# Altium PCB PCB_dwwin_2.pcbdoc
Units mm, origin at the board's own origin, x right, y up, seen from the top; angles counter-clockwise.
Board outline 160.3 x 97.45 mm, 2 copper layers (Top Layer, Bottom Layer); 27 components, 25 nets, 175 pads, 0 vias.
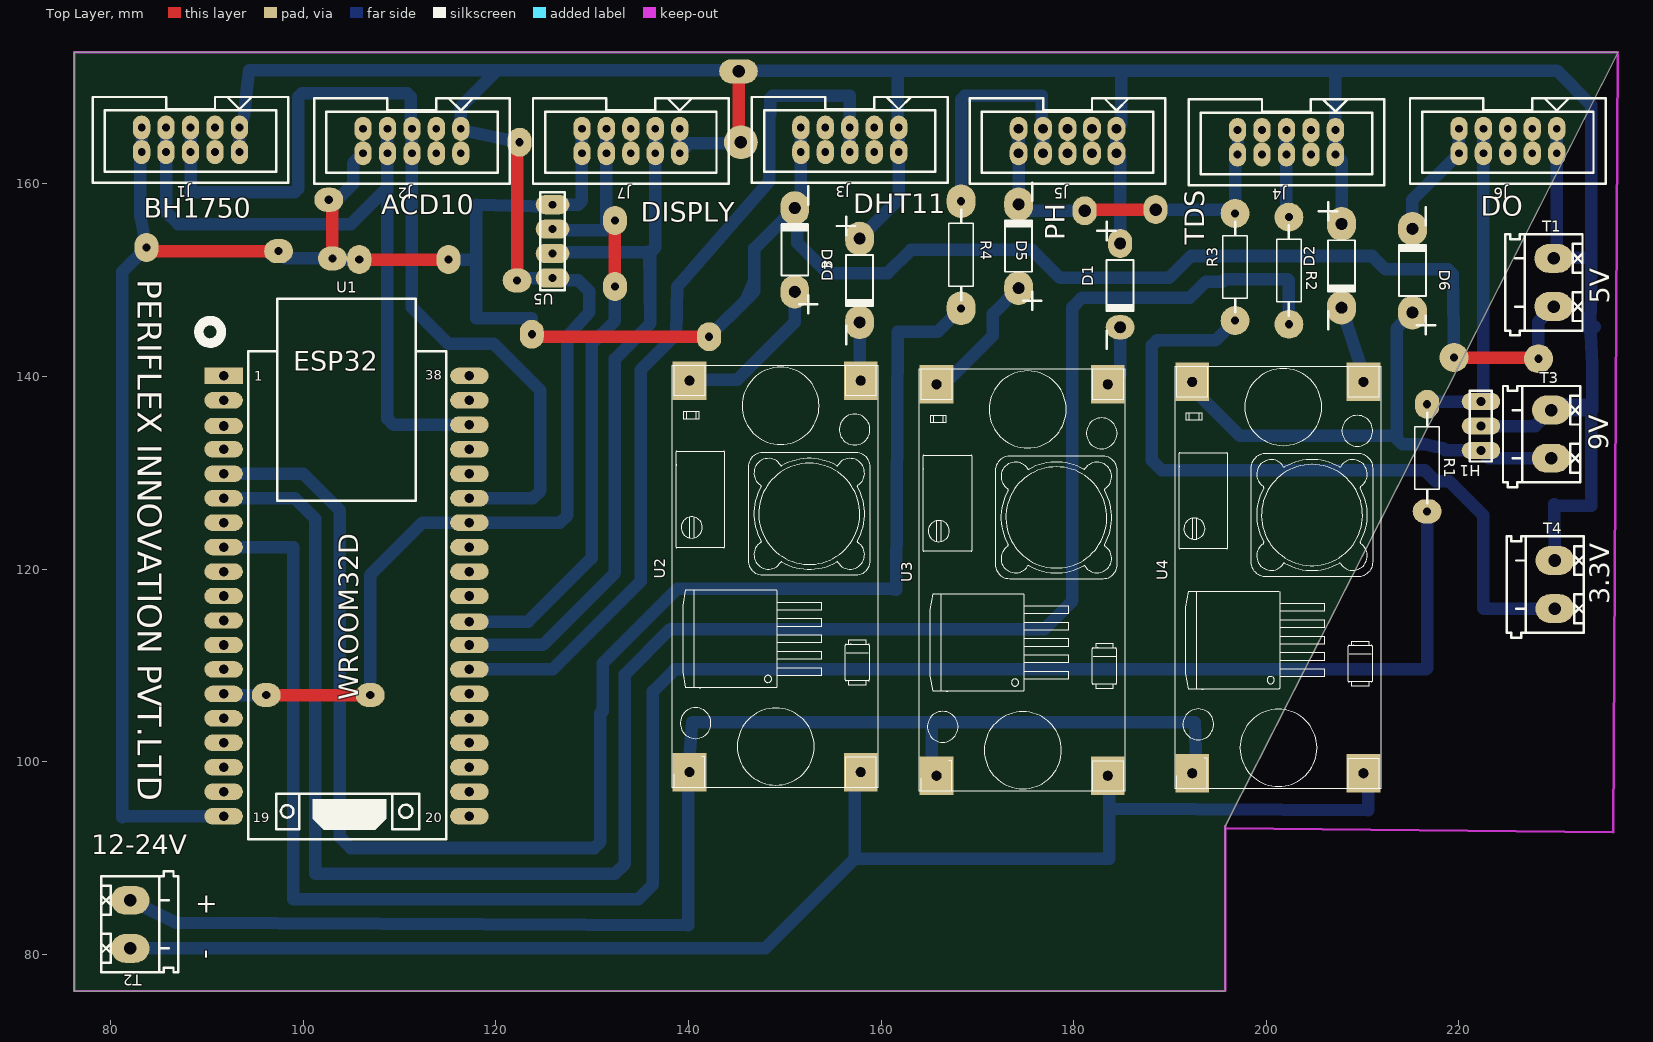
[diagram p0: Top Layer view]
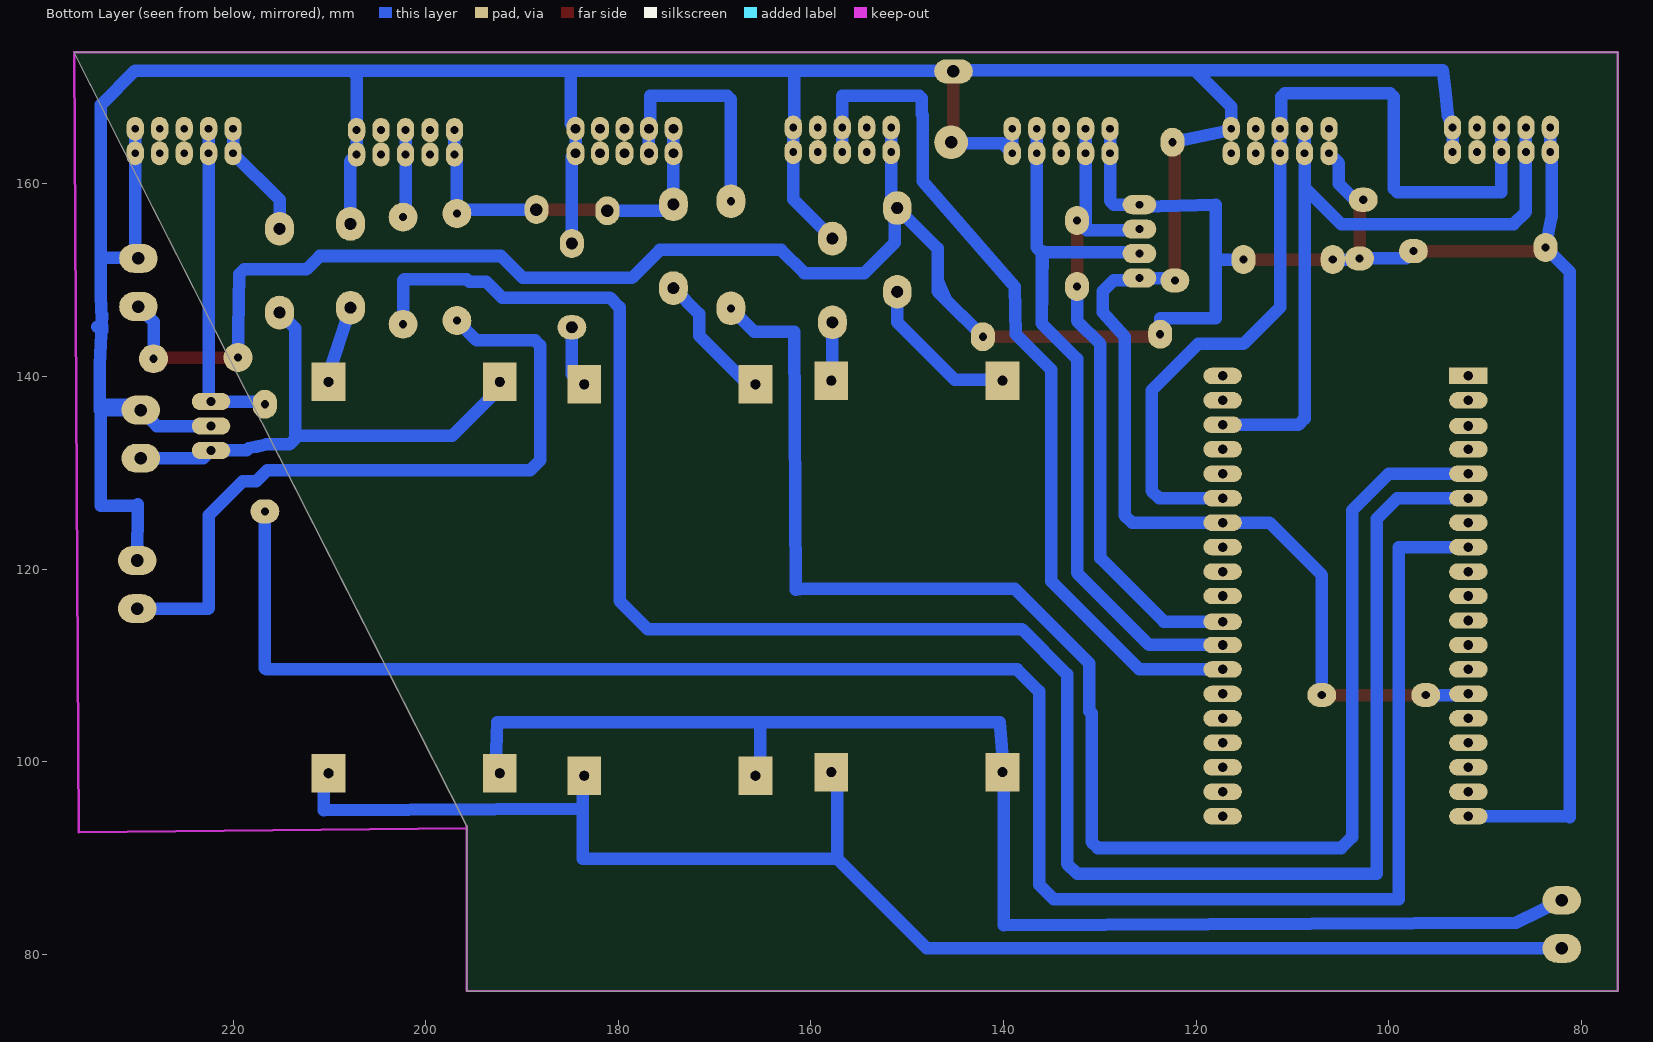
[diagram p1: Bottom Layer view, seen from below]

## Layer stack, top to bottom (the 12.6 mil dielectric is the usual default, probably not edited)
Top Layer: signal copper (thickness not stored)
Dielectric: dielectric 0.32, FR-4, Dk 4.8
Bottom Layer: signal copper (thickness not stored)

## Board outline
195.738,93.335 195.738,76.2 76.2,76.2 76.2,173.655 236.505,173.655

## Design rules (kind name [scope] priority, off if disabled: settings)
BoardOutlineClearance Default [All] p0: genericclearance=0.254 ignorepadtopadclearanceinfootprint=FALSE except(0: Region-CutoutEdge Arc-SplitContinuation Track-SplitContinuation SMDPad-SplitContinuation THPad-SplitContinuation Via-SplitContinuation Fill-SplitContinuation Poly-SplitContinuation Region-SplitContinuation Text-SplitContinuation; 0.5: Track-OutlineEdge SMDPad-OutlineEdge THPad-OutlineEdge Via-OutlineEdge Fill-OutlineEdge Region-OutlineEdge Poly-OutlineEdge Text-OutlineEdge Sheet-OutlineEdge Hole-OutlineEdge Track-CutoutEdge SMDPad-CutoutEdge THPad-CutoutEdge Via-CutoutEdge Fill-CutoutEdge Poly-CutoutEdge Text-CutoutEdge Sheet-CutoutEdge Hole-CutoutEdge)
Clearance Default [All] p1: gap=0.178 ignorepadtopadclearanceinfootprint=FALSE except(0: Region-Region; 0.5: Track-Track SMDPad-Track THPad-Track Via-Track Fill-Track Region-Track Poly-Track Text-Track Sheet-Track Hole-Track Track-SMDPad SMDPad-SMDPad THPad-SMDPad Via-SMDPad Fill-SMDPad Region-SMDPad Poly-SMDPad Text-SMDPad Sheet-SMDPad Hole-SMDPad Track-THPad SMDPad-THPad THPad-THPad Via-THPad Fill-THPad Region-THPad Poly-THPad Text-THPad Sheet-THPad Hole-THPad Track-Via SMDPad-Via THPad-Via Via-Via Fill-Via Region-Via Poly-Via Text-Via Sheet-Via Hole-Via Track-Fill SMDPad-Fill THPad-Fill Via-Fill Fill-Fill Region-Fill Poly-Fill Text-Fill Sheet-Fill Hole-Fill Track-Region SMDPad-Region THPad-Region Via-Region Fill-Region Poly-Region Text-Region Sheet-Region Hole-Region Track-Poly SMDPad-Poly THPad-Poly Via-Poly Fill-Poly Region-Poly Poly-Poly Text-Poly Sheet-Poly Hole-Poly Track-Text SMDPad-Text THPad-Text Via-Text Fill-Text Region-Text Poly-Text Text-Text Sheet-Text Hole-Text Track-Sheet SMDPad-Sheet THPad-Sheet Via-Sheet Fill-Sheet Region-Sheet Poly-Sheet Text-Sheet Sheet-Sheet Hole-Sheet Track-Hole SMDPad-Hole THPad-Hole Via-Hole Fill-Hole Region-Hole Poly-Hole Text-Hole Sheet-Hole Hole-Hole)
PasteMaskExpansion Common [All] p1: expansion=0
PlaneConnect Default [All] p1: planeconnectstyle=Relief reliefexpansion=0.508 reliefentries=4 reliefconductorwidth=0 reliefairgap=0.025
PolygonConnect Default [All] p1: connectstyle=Relief reliefentries=4 reliefconductorwidth=0 polygonreliefangle="90 Angle" airgapwidth=10
RoutingVias Default [All] p1: viastyle="Through Hole" holewidth=12.008000000000001 minholewidth=12.008000000000001 maxholewidth=2362 width=24.016000000000002 minwidth=24.016000000000002 maxwidth=3938
SolderMaskExpansion Common [All] p1: useseparateexpansions=TRUE expansion=2 expansionbottom=2
Width Default [All] p1: maxlimit=1000 minlimit=51 preferedwidth=51

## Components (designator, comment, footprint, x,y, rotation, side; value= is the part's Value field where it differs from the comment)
D1 "1N4007G-K COPY" DO-204AL_BD2.4-L4.7-P8.70-D1.1-RD#1 184.816,149.469 r90 top
D2 "1N4007G-K COPY" DO-204AL_BD2.4-L4.7-P8.70-D1.1-RD#2 207.803,151.501 r90 top
D3 "1N4007G-K COPY" DO-204AL_BD2.4-L4.7-P8.70-D1.1-RD#2 157.765,149.977 r90 top
D4 "1N4007G-K COPY" DO-204AL_BD2.4-L4.7-P8.70-D1.1-RD#2 151.034,153.152 r270 top
D5 "1N4007G-K COPY" DO-204AL_BD2.4-L4.7-P8.70-D1.1-RD#2 174.275,153.533 r270 top
D6 "1N4007G-K COPY" DO-204AL_BD2.4-L4.7-P8.70-D1.1-RD#2 215.169,150.993 r270 top
H1 "aux do" HEADER3X1 222.281,132.324 r180 top
J1 "bh1750" FRC10#1 85.756,164.582 r180 top
J2 "acd10(co2)" FRC10#1 108.743,164.455 r180 top
J3 "dht11" FRC10#1 154.209,164.582 r180 top
J4 "tds sensor" FRC10#1 199.548,164.328 r180 top
J5 "ph sensor" FRC10#2 176.815,164.455 r180 top
J6 "do sensor" FRC10#1 222.535,164.455 r180 top
J7 "lcd" FRC10#1 131.476,164.455 r180 top
R1 "10" RES-TH_BD2.4-L6.4-P11.12-D0.6#1 216.693,131.562 r270 top
R2 "470Ω" RES-TH_BD2.4-L6.4-P11.12-D0.6#2 202.342,150.993 r270 top
R3 "470Ω" RES-TH_BD2.4-L6.4-P11.12-D0.6#2 196.754,151.374 r90 top
R4 "470Ω" RES-TH_BD2.4-L6.4-P11.12-D0.6#3 168.306,152.644 r270 top
T1 "5v" "M02 SCREW TERMINAL 5MM 10X8MM" 224.821,144.77 r0 top
T2 "main 12-24v dc" "M02 SCREW TERMINAL 5MM 10X8MM" 87.026,88.128 r180 top
T3 "9v" "M02 SCREW TERMINAL 5MM 10X8MM" 224.567,129.022 r0 top
T4 "SCREW TERMINAL COPY" "M02 SCREW TERMINAL 5MM 10X8MM" 224.948,113.401 r0 top
U1 "WROOM32D-38 COPY" WROOM32D 91.725,140.071 r0 top
U2 "5v" LM2596:YAAJ_DCDC_STEPDOWN_LM2596 140.101,98.934 r90 top
U3 "3.3" LM2596:YAAJ_DCDC_STEPDOWN_LM2596 165.755,98.553 r90 top
U4 "9" LM2596:YAAJ_DCDC_STEPDOWN_LM2596 192.298,98.807 r90 top
U5 "aux lcd" HEADER4 125.888,154.041 r180 top

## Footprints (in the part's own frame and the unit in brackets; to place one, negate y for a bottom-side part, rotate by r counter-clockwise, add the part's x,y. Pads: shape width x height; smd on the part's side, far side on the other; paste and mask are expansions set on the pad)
DO-204AL_BD2.4-L4.7-P8.70-D1.1-RD#1 [mm]
  oval 2.5x3 hole 1.2 slot 1.205 at 90 deg: 1(-4.35,0)
  oval 3x2.5 hole 1.2 slot 1.205 at 0 deg: 2(4.35,0)
  silkscreen extent -6.6,-1.4 6.6,2.35
DO-204AL_BD2.4-L4.7-P8.70-D1.1-RD#2 [mm]
  oval 3.5x3 hole 1.2 slot 1.205 at 0 deg: 1(-4.35,0) 2(4.35,0)
  silkscreen extent -6.6,-1.4 6.6,2.35
FRC10#1 [mm]
  oval 1.8x2.5 hole 0.8: 1(-7.62,-1.27) 2(-7.62,1.27) 3(-5.08,-1.27) 4(-5.08,1.27) 5(-2.54,-1.27) 6(-2.54,1.27) 7(0,-1.27) 8(0,1.27) 9(2.54,-1.27) 10(2.54,1.27)
  silkscreen extent -12.7,-4.45 7.62,4.45
FRC10#2 [mm]
  oval 1.85x2.5 hole 1.021: 1(-7.62,-1.27) 2(-7.62,1.27) 3(-5.08,-1.27) 4(-5.08,1.27) 5(-2.54,-1.27) 6(-2.54,1.27) 7(0,-1.27) 8(0,1.27) 9(2.54,-1.27) 10(2.54,1.27)
  silkscreen extent -12.7,-4.45 7.62,4.45
HEADER3X1 [mm]
  oval 4x1.8 hole 0.914: 1(0,0) 2(0,-2.54) 3(0,-5.08)
  silkscreen extent -1.14,-6.22 1.14,1.14
HEADER4 [mm]
  oval 3.5x2 hole 0.8: 1(0,3.81) 2(0,1.27) 3(0,-1.27) 4(0,-3.81)
  silkscreen extent -1.27,-5.08 1.27,5.08
LM2596:YAAJ_DCDC_STEPDOWN_LM2596 [mm]
  rect 4x3.5 hole 1 slot 1.005 at 0 deg: 1(0,0) 2(0,-17.78) 3(40.64,-17.78) 4(40.64,0)
  silkscreen extent -1.55,-19.61 42.22,1.83
"M02 SCREW TERMINAL 5MM 10X8MM" [mm]
  oval 4x3 hole 1.3: 1(5,7.5) 2(5,2.5)
  silkscreen extent 0,-0.5 8,10
RES-TH_BD2.4-L6.4-P11.12-D0.6#1 [mm]
  oval 3x2.5 hole 0.84: 1(-5.56,0)
  oval 2.5x3 hole 0.84: 2(5.56,0)
  silkscreen extent -4.7,-1.27 4.7,1.27
RES-TH_BD2.4-L6.4-P11.12-D0.6#2 [mm]
  round 3 hole 0.84: 1(-5.56,0) 2(5.56,-0.001)
  silkscreen extent -4.7,-1.27 4.7,1.27
RES-TH_BD2.4-L6.4-P11.12-D0.6#3 [mm]
  oval 3.5x3 hole 0.84: 1(-5.56,0) 2(5.56,0)
  silkscreen extent -4.7,-1.27 4.7,1.27
WROOM32D [mm]
  rect 4x1.7 hole 1: 1(0,0)
  oval 4x1.7 hole 1: 2(0,-2.54) 3(0,-5.207) 4(0,-7.62) 5(0,-10.16) 6(0,-12.7) 7(0,-15.24) 8(0,-17.78) 9(0,-20.32) 10(0,-27.94) 10(0,-22.86) 11(0,-25.4) 13(0,-30.48) 14(0,-33.02) 15(0,-35.56) 16(0,-38.1) 17(0,-40.64) 18(0,-43.18) 19(0,-45.72) 20(25.527,-45.72) 21(25.527,-43.18) 22(25.527,-40.64) 23(25.527,-38.1) 24(25.527,-35.56) 25(25.527,-33.02) 26(25.527,-30.48) 27(25.527,-27.94) 28(25.527,-25.527) 29(25.527,-22.86) 30(25.527,-20.32) 31(25.527,-17.78) 32(25.527,-15.24) 33(25.527,-12.7) 34(25.527,-10.16) 35(25.527,-7.62) 36(25.527,-5.08) 37(25.527,-2.54) 38(25.527,0)
  silkscreen extent -2.56,-48.13 23.11,8

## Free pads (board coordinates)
  round 3.5 hole 1.3: 1(145.445,164.328)
  oval 4x2.5 hole 1.3: 2(145.192,171.694)
  round 3 hole 0.84: 3(219.487,141.976) 4(228.25,141.849)
  oval 2.5x3 hole 1.3: 5(188.499,157.343) 6(181.133,157.216)
  oval 3x2.5 hole 0.84: 7(97.44,153.025) 13(122.205,149.977) 25(102.647,158.359) 26(103.028,152.263) 30(96.159,106.935) 31(106.954,106.934)
  oval 2.5x3 hole 0.84: 8(83.724,153.406) 15(122.459,164.328) 20(132.365,156.2) 22(132.365,149.342) 23(123.729,144.389) 24(142.144,144.135) 27(105.811,152.147) 28(115.082,152.147)

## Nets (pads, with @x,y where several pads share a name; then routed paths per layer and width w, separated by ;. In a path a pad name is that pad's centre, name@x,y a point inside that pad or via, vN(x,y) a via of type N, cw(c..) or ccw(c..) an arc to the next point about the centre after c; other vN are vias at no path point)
3.3: D5.1 J4.9 J4.10 J5.9 J5.10 pad.5 pad.6 R3.2 | length 39.7
  Top Layer w1.3: pad.6 181.26,157.343 pad.5
  Bottom Layer w1.3: D5.1 J5.10 J5.9 ; D5.1 174.943,157.216 pad.6 pad.6@181.133,157.343 ; pad.5 196.344,157.343 R3.2 196.753,162.803 J4.10 J4.9
9: D6.1 J6.9 J6.10 | length 12.4
  Bottom Layer w1.3: D6.1 215.169,158.359 J6.10 J6.9
+5V: D4.1 J1.9 J1.10 J2.10 J3.9 J3.10 J7.9 J7.10 pad.3 pad.4 pad.7 pad.8 pad.23 pad.24 pad.25 pad.26 pad.27 pad.28 T1.2 U1.19 U5.4 | length 320.6
  Top Layer w1.3: pad.8 84.105,153.025 pad.7 ; pad.25 103.028,157.978 pad.26 ; pad.27 pad.28 ; pad.23 123.983,144.135 pad.24 ; pad.3 228.123,141.976 pad.4
  Bottom Layer w1.3: J1.9 J1.10 83.089,163.185 83.089,156.581 pad.8 81.184,150.866 81.184,94.224 81.311,94.351 U1.19 ; pad.7 98.202,152.263 pad.26 103.144,152.147 pad.27@105.176,152.147 ; pad.25 103.536,158.359 105.187,160.01 105.187,162.169 J2.10 ; pad.28 117.908,152.147 117.968,152.087 ; pad.23 123.729,146.05 117.968,146.05 117.968,157.851 125.644,157.608 U5.4 128.555,157.851 128.936,158.232 J7.10 J7.9 ; 146.716,149.723 145.954,147.945 pad.24 146.843,148.834 146.843,153.311 D4.1 151.669,158.137 J3.10 J3.9 ; D4.1 151.288,157.249 151.288,153.914 154.452,150.749 160.675,150.749 163.078,153.152 175.672,153.152 178.582,150.241 189.906,150.241 192.182,152.517 210.978,152.517 212.375,151.12 218.852,151.12 219.36,150.612 pad.3 ; pad.4 228.25,145.699 T1.2
A/O1: R2.2 U1.6 | length 207.9
  Bottom Layer w1.3: U1.6 99.091,127.371 101.25,125.212 101.25,120.386 101.25,88.382 132.365,88.382 133.381,89.398 133.381,109.083 138.08,113.782 176.942,113.782 179.863,116.703 179.863,147.183 180.879,148.199 192.055,148.199 193.706,149.85 195.484,149.85 195.738,150.104 202.215,150.104 202.341,149.977 R2.2
A/O2: R4.2 U1.5 | length 162.1
  Bottom Layer w1.3: U1.5 99.98,129.911 103.79,126.101 103.79,92.192 104.933,91.049 130.206,91.049 130.841,91.684 130.841,105.019 131.095,105.273 131.095,110.226 138.842,117.973 160.686,117.973 161.564,117.857 161.702,144.643 165.865,144.643 R4.2
DATA1: J3.5 J3.6 U1.26 | length 91.1
  Bottom Layer w1.3: U1.26 125.888,109.591 135.032,118.735 135.032,140.706 138.715,144.389 138.842,149.342 148.367,160.264 148.367,167.122 148.494,167.249 148.494,168.9 148.748,169.154 156.749,169.154 J3.5 J3.6
DO: R1.2 U1.8 | length 201
  Bottom Layer w1.3: U1.8 98.953,122.302 98.953,120.894 ; R1.2 216.693,109.718 216.566,109.591 138.588,109.591 136.302,107.305 136.302,87.239 134.778,85.715 98.953,85.715 98.953,119.967 98.953,120.894 ; 98.953,120.894 98.953,120.143 98.953,120.894
GND: D1.2 D2.2 D3.2 H1.2 J1.1 J1.2 J2.1 J3.1 J3.2 J4.1 J4.2 J5.1 J5.2 J6.1 J6.2 J7.1 J7.2 pad.1 pad.2 pad.13 pad.15 pad.30 pad.31 T1.1 T3.1 T4.1 U1.14 U1.32 U1.38 U5.1 | length 420.1
  Top Layer w1.3: pad.30 pad.31 ; pad.13 122.205,164.074 pad.15 ; pad.2 145.192,164.201 pad.1@145.319,164.201
  Bottom Layer w1.3: U1.14 91.725,106.934 pad.30 ; J1.2 J1.1 93.884,167.249 94.138,169.789 94.392,171.821 120.16,171.821 ; pad.31 106.954,119.38 112.405,124.831 U1.32 126.65,124.831 127.412,125.593 127.412,144.135 129.698,146.675 129.698,148.834 128.555,149.977 126.142,149.977 U5.1 122.205,150.231 pad.13 ; 116.363,167.782 J2.1 116.363,165.598 pad.15 ; 116.364,168.025 120.16,171.821 ; J7.1 J7.2 140.112,164.201 pad.1@145.319,164.201 ; pad.2@145.143,171.765 230.16,171.765 233.711,168.214 233.711,148.293 233.584,144.77 234.092,145.151 ; pad.2@145.192,171.821 120.16,171.821 ; D3.2 161.828,158.391 J3.2 J3.1 161.706,165.975 161.706,171.765 ; D1.2 184.816,162.804 J5.2 J5.1 184.947,166.237 184.947,171.765 ; 207.68,171.765 207.168,171.253 207.168,167.597 J4.1 J4.2 207.841,162.372 D2.2 207.841,155.852 D2.2 ; H1.2 227.908,134.864 T3.1 ; 229.901,126.736 T4.1@229.947,120.894 ; 229.947,126.406 229.949,126.609 233.711,126.609 233.711,137.084 230.127,137.084 T3.1 233.838,136.522 233.838,141.323 233.584,146.421 ; J6.1 J6.2 230.154,152.604 229.82,152.27 229.889,152.338 233.711,152.338
J4_5: J4.5 J4.6 R2.1 | length 9.3
  Bottom Layer w1.3: J4.5 J4.6 202.088,156.553 R2.1
J5_7: J5.7 J5.8 R4.1 | length 25.1
  Bottom Layer w1.3: R4.1 168.306,168.773 168.687,169.154 176.688,169.154 176.688,165.852 J5.7 J5.8
J6_7: H1.3 J6.7 J6.8 R1.1 | length 34.1
  Bottom Layer w1.3: R1.1 216.974,137.404 H1.3 222.534,137.658 J6.8 J6.7
RX: J7.3 J7.4 U1.27 U5.2 | length 90
  Bottom Layer w1.3: U1.27 124.872,112.131 132.365,119.624 132.365,141.849 136.048,145.532 135.921,153.025 136.048,146.167 136.048,152.898 ; U5.2 126.015,152.898 136.048,152.898 ; J7.3 J7.4 136.556,153.406 136.048,152.898
S$13850: U1.29
SCL1: J1.7 J1.8 J2.7 J2.8 U1.36 | length 72.7
  Bottom Layer w1.3: J1.7 J1.8 85.756,157.089 87.026,155.819 104.933,155.819 108.743,159.629 ; J2.7 J2.8 108.743,159.629 ; U1.36 109.378,134.991 108.743,135.626 108.743,159.629
SDA1: J1.5 J1.6 J2.5 J2.6 U1.33 | length 96.5
  Bottom Layer w1.3: J1.5 J1.6 88.296,159.121 99.091,159.121 99.472,159.502 99.472,169.027 99.853,169.408 110.775,169.408 111.156,169.027 111.156,165.852 J2.5 J2.6 111.283,147.183 115.082,143.383 119.781,143.383 124.607,138.557 124.607,128.143 123.835,127.371 U1.33
T3_2: D6.2 H1.1 T3.2 U4.4 | length 54.1
  Bottom Layer w1.3: U4.4@192.436,139.436 192.436,138.674 197.262,133.848 213.264,133.848 ; D6.2 213.518,144.991 213.518,133.594 214.153,132.959 216.566,132.959 217.582,132.705 218.344,132.578 218.598,132.324 H1.1 223.082,131.522 T3.2
T4_2: R3.1 T4.2 | length 75.5
  Bottom Layer w1.3: R3.1 194.693,143.754 188.626,143.754 188.118,143.246 188.118,131.308 189.134,130.292 216.439,130.292 217.582,129.149 218.979,129.149 222.535,125.593 222.535,115.941 222.574,115.901 T4.2
TX: J7.7 J7.8 pad.20 pad.22 U1.28 U5.3 | length 69.4
  Top Layer w1.3: pad.22 pad.20
  Bottom Layer w1.3: U1.28 123.348,114.544 129.952,121.148 129.952,143.373 132.365,145.786 pad.22 pad.22@132.238,149.342 ; U5.3 126.015,155.184 131.349,155.184 pad.20@131.476,155.311 ; J7.7 J7.8 pad.20@131.476,155.311 ; pad.20@132.746,156.2 pad.20 pad.20@131.476,155.311
U2_3: D3.1 U2.3 | length 5.9
  Bottom Layer w1.3: U2.3@157.764,139.69 D3.1
U2_4: D4.2 U2.4 | length 16.7
  Bottom Layer w1.3: U2.4@139.985,139.69 145.065,139.69 151.034,145.659 D4.2
U3_1: T2.2 U2.1 U3.1 U4.1 | length 144
  Bottom Layer w1.3: T2.2@82.024,85.628 86.772,83.302 139.985,83.048 139.985,99.05 140.366,104.13 165.385,104.13 ; U3.1@165.755,98.299 165.258,98.299 165.258,104.003 165.385,104.13 ; U4.1@192.563,98.796 192.69,98.542 192.69,101.209 192.563,104.13 165.385,104.13
U3_2: T2.1 U2.2 U3.2 U4.2 | length 157.5
  Bottom Layer w1.3: T2.1@82.024,80.627 147.968,80.627 157.257,89.916 ; 157.257,95.573 U2.2@157.257,98.542 ; U3.2@183.673,98.161 183.673,89.916 157.257,89.916 ; 183.8,95.113 210.597,94.986 210.597,98.542 U4.2@210.343,98.796 ; 157.257,89.916 U2.2@157.257,98.542 ; U2.2@157.257,98.542 157.765,99.05 U2.2@157.257,98.542
U3_3: D1.1 U3.3 | length 6.7
  Bottom Layer w1.3: U3.3@183.535,138.939 184.816,140.219 D1.1
U3_4: D5.2 U3.4 | length 14.1
  Bottom Layer w1.3: U3.4@165.755,138.939 166.284,138.939 171.608,144.262 171.608,146.516 D5.2
U4_3: D2.1 U4.3 | length 8.1
  Bottom Layer w1.3: D2.1 U4.3@210.343,139.436
pads on no net: J1.3 J1.4 J2.2 J2.3 J2.4 J2.9 J3.3 J3.4 J3.7 J3.8 J4.3 J4.4 J4.7 J4.8 J5.3 J5.4 J5.5 J5.6 J6.3 J6.4 J6.5 J6.6 J7.5 J7.6 U1.1 U1.2 U1.3 U1.4 U1.7 U1.9 U1.10 U1.11 U1.13 U1.15 U1.16 U1.17 U1.18 U1.20 U1.21 U1.22 U1.23 U1.24 U1.25 U1.30 U1.31 U1.34 U1.35 U1.37

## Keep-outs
Board Outline Layer:
  lines w0.254: 195.738,93.081 235.997,92.7 236.505,173.401 ; 195.738,93.335 195.738,76.2 76.2,76.2 76.2,173.655 236.505,173.655

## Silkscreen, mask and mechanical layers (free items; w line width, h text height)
Top Silkscreen Layer:
  text "DHT11" at 157.119,156.973 h2.03
  text "ACD10" at 108.097,156.846 h2.03
  text "DO" at 222.27,156.719 h2.03
  text "BH1750" at 83.459,156.465 h2.03
  text "DISPLY" at 135.021,156.084 h2.03
  text "PH" at 179.09,154.179 h2.03 r90
  text "TDS" at 193.568,153.671 h2.03 r90
  text "PERIFLEX INNOVATION PVT.LTD" at 82.824,150.115 h2.5 r270
  text "5V" at 235.605,147.575 h2.03 r90
  text "9V" at 235.478,132.335 h2.03 r90
  text "3.3V" at 235.605,116.333 h2.03 r90
  text "12-24V" at 77.998,90.425 h2.03
  text "+" at 88.793,84.329 h2.03
  text "-" at 90.698,79.503 h2.03 r90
